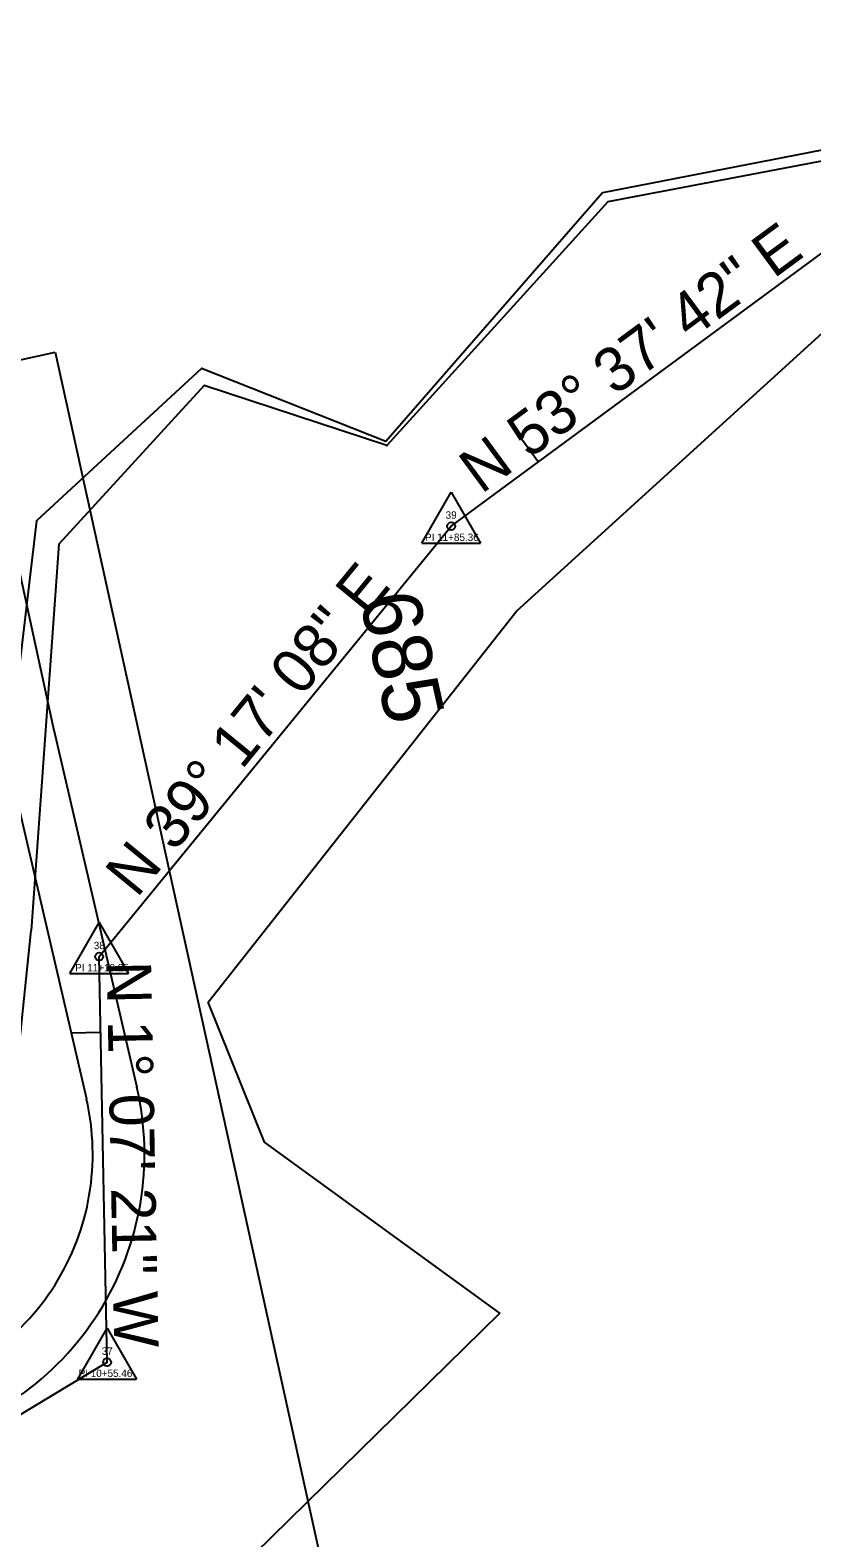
# Model space of a CAD drawing. Extents: x 2519952 to 2531965, y 848341 to 887632.
# Drawn here: x 2524306.9 to 2524412.5, y 857048.4 to 857252 of the extents above; entities that cross this region are included whole.
import ezdxf

# ---------------------------------------------------------------- set-up
doc = ezdxf.new("R2010")
doc.units = 0
for name, color, linetype in [('RD_EX_DV_Prop', 7, 'Continuous'), ('RD_EX_H2O', 7, 'Continuous'), ('RD_EX_Misc', 7, 'Continuous'), ('RD_EX_RW', 7, 'Continuous'), ('RD_HC_Cl', 7, 'Continuous'), ('RD_HC_Data', 7, 'Continuous'), ('RD_HC_Data_Tic', 7, 'Continuous'), ('RD_HC_TX_Sta50', 7, 'Continuous'), ('RD_HC_txCode', 7, 'Continuous'), ('RD_PD_BCA', 7, 'Continuous'), ('RD_PD_DR_ErosCtrl', 7, 'Continuous'), ('RD_SMD_Locator', 7, 'Continuous')]:
    doc.layers.add(name, color=color, linetype=linetype)

msp = doc.modelspace()

# ---------------------------------------------------------------- linework, layer by layer
at = {"layer": 'RD_EX_DV_Prop'}
for p, q in [((2524363.75, 857185), (2524418.64, 857225.44)), ((2524273.61, 857200.43), (2524310.23, 857208.49)), ((2524310.23, 857208.49), (2524374.75, 856915.51)), ((2524325.66, 857138.44), (2524363.75, 857185))]:
    msp.add_line(p, q, dxfattribs=at)
at = {"layer": 'RD_EX_H2O'}
for points in [[(2524325.32, 857034.6), (2524370.33, 857078.7), (2524338.52, 857101.81), (2524330.9, 857120.7), (2524372.59, 857173.51), (2524416.97, 857213.86), (2524460.94, 857209.24), (2524489.14, 857193.54), (2524517.47, 857203.86), (2524519.61, 857206.94), (2524538.32, 857212.06), (2524571.31, 857226.09), (2524634.31, 857245.44), (2524679.87, 857306.36)], [(2524544.94, 857088.92), (2524516.45, 857137.55), (2524537.31, 857176.49), (2524512.04, 857215.4), (2524463.34, 857250.07), (2524420.69, 857235.6), (2524384.92, 857228.78), (2524355.07, 857195.87), (2524330.4, 857204.01), (2524310.75, 857182.57), (2524307.01, 857130.38)], [(2524218.99, 857071.27), (2524223.78, 857062.61), (2524296.44, 857076.06), (2524302.51, 857087.07), (2524307.01, 857130.38)]]:
    msp.add_lwpolyline(points, dxfattribs=at)
at = {"layer": 'RD_EX_Misc'}
msp.add_lwpolyline([(2524546.39, 857089.12), (2524517.38, 857137.92), (2524538.03, 857176.84), (2524519.61, 857206.94), (2524513, 857216.34), (2524463.61, 857251.75), (2524420.32, 857237.04), (2524384.22, 857230.02), (2524354.94, 857196.44), (2524330.04, 857206.28), (2524307.73, 857185.7), (2524301.47, 857133.05)], dxfattribs=at)
at = {"layer": 'RD_EX_RW'}
for p, q in [((2524273.61, 857200.42), (2524310.23, 857208.49)), ((2524310.23, 857208.49), (2524374.75, 856915.51))]:
    msp.add_line(p, q, dxfattribs=at)
at = {"layer": 'RD_HC_Cl'}
for p, q in [((2524363.75, 857185), (2524418.64, 857225.44)), ((2524316.19, 857126.87), (2524363.75, 857185)), ((2524317.26, 857072.09), (2524316.19, 857126.87)), ((2524152.13, 856972.4), (2524317.26, 857072.09))]:
    msp.add_line(p, q, dxfattribs=at)
at = {"layer": 'RD_HC_Data'}
for p, q in [((2524359.78, 857182.71), (2524363.75, 857189.59)), ((2524363.75, 857189.59), (2524367.72, 857182.71)), ((2524359.78, 857182.71), (2524367.72, 857182.71)), ((2524312.22, 857124.58), (2524316.19, 857131.46)), ((2524316.19, 857131.46), (2524320.16, 857124.58)), ((2524312.22, 857124.58), (2524320.16, 857124.58)), ((2524313.29, 857069.8), (2524317.26, 857076.68)), ((2524317.26, 857076.68), (2524321.23, 857069.8)), ((2524313.29, 857069.8), (2524321.23, 857069.8))]:
    msp.add_line(p, q, dxfattribs=at)
for centre in [(2524363.75, 857185), (2524316.19, 857126.87), (2524317.26, 857072.09)]:
    msp.add_circle(centre, 0.529, dxfattribs=at)
at = {"layer": 'RD_HC_Data_Tic'}
for p, q in [((2524375.53, 857193.68), (2524373.16, 857196.9)), ((2524316.39, 857116.61), (2524312.39, 857116.54))]:
    msp.add_line(p, q, dxfattribs=at)
at = {"layer": 'RD_PD_BCA'}
for p, q in [((2524304.78, 857181.69), (2524310.13, 857157.24)), ((2524310.08, 857157.49), (2524321.28, 857109.22))]:
    msp.add_line(p, q, dxfattribs=at)
msp.add_arc((2524282.32, 857100.17), 40, 282.4185, 13.0724, dxfattribs=at)
at = {"layer": 'RD_PD_DR_ErosCtrl'}
msp.add_line((2524303.26, 857155.91), (2524314.47, 857107.64), dxfattribs=at)
msp.add_arc((2524282.32, 857100.17), 33, 282.4185, 13.0724, dxfattribs=at)
at = {"layer": 'RD_SMD_Locator'}
for centre in [(2524384.22, 857230.02), (2524384.92, 857228.78), (2524330.04, 857206.28), (2524330.4, 857204.01), (2524354.94, 857196.44), (2524355.07, 857195.87), (2524307.73, 857185.7), (2524363.75, 857185), (2524310.75, 857182.57), (2524372.59, 857173.51), (2524307.01, 857130.38), (2524307.01, 857130.38), (2524316.19, 857126.87), (2524330.9, 857120.7), (2524338.52, 857101.81), (2524370.33, 857078.7), (2524317.26, 857072.09)]:
    msp.add_circle(centre, 0.001, dxfattribs=at)

# ---------------------------------------------------------------- texts
at = {"layer": 'RD_HC_Data'}
for s, rotation, p in [('N 53%%d 37\' 42" E', 36.3717, (2524367.82, 857189.25)), ('N 39%%d 17\' 08" E', 50.7144, (2524321.28, 857134.67)), ('N 1%%d 07\' 21" W', 271.1226, (2524317.2, 857126.21))]:
    msp.add_text(s, height=6, rotation=rotation, dxfattribs=at).set_placement(p)
at = {"layer": 'RD_HC_TX_Sta50'}
msp.add_text('685', height=8, rotation=282.4185, dxfattribs=at).set_placement((2524351.34, 857175.25))
at = {"layer": 'RD_HC_txCode'}
for s, p in [('39', (2524363.01, 857186)), ('PI 11+85.36', (2524360.23, 857183)), ('38', (2524315.46, 857127.87)), ('PI 11+10.25', (2524312.94, 857124.87)), ('37', (2524316.53, 857073.09)), ('PI 10+55.46', (2524313.42, 857070.09))]:
    msp.add_text(s, height=1, dxfattribs=at).set_placement(p)

doc.saveas('drawing.dxf')
